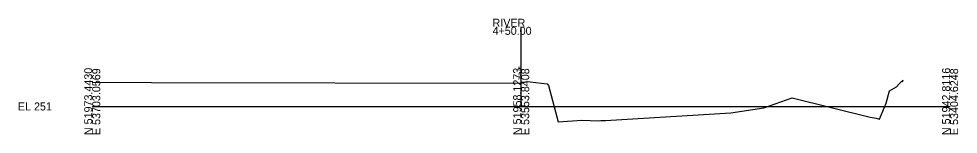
# Model space of a CAD drawing. Extents: x 5628 to 5956, y 92469 to 104012.
# Drawn here: x 5627.6 to 5956.2, y 93968.9 to 94009.2 of the extents above; entities that cross this region are included whole.
import ezdxf

# ---------------------------------------------------------------- set-up
doc = ezdxf.new("R2010")
doc.units = 0
for name, color, linetype in [('Level 10', 7, 'Continuous'), ('Level 60', 7, 'Continuous'), ('Level 63', 7, 'Continuous')]:
    doc.layers.add(name, color=color, linetype=linetype)

msp = doc.modelspace()

# ---------------------------------------------------------------- linework, layer by layer
at = {"layer": 'Level 60'}
for p, q in [((5653.34, 93987.08), (5674.06, 93986.92)), ((5674.06, 93986.92), (5802.45, 93986.7)), ((5802.45, 93986.7), (5803.34, 93986.7)), ((5803.34, 93986.7), (5804.95, 93987.23)), ((5804.95, 93987.23), (5805.38, 93987.35)), ((5805.38, 93987.35), (5806.47, 93987.21)), ((5806.47, 93987.21), (5812.44, 93986.46)), ((5812.44, 93986.46), (5812.92, 93985.94)), ((5934.64, 93985.48), (5935.58, 93986.47)), ((5935.58, 93986.47), (5936.41, 93987.44)), ((5936.41, 93987.44), (5936.73, 93987.24)), ((5936.73, 93987.24), (5936.97, 93987.87)), ((5812.92, 93985.94), (5816.27, 93973.28)), ((5931.03, 93979.72), (5932.18, 93984)), ((5932.18, 93984), (5934.64, 93985.48)), ((5888.18, 93978.07), (5898.12, 93981.63)), ((5898.12, 93981.63), (5925.36, 93974.86)), ((5876.68, 93976.31), (5888.18, 93978.07)), ((5928.6, 93974.16), (5931.03, 93979.72)), ((5816.27, 93973.28), (5824.54, 93973.78)), ((5824.54, 93973.78), (5830.39, 93973.53)), ((5830.39, 93973.53), (5831.15, 93973.72)), ((5831.15, 93973.72), (5832.83, 93973.74)), ((5832.83, 93973.74), (5876.68, 93976.31)), ((5925.36, 93974.86), (5927.49, 93974.52)), ((5927.49, 93974.52), (5928.6, 93974.16))]:
    msp.add_line(p, q, dxfattribs=at)
at = {"layer": 'Level 63'}
for p, q in [((5803.34, 93978.6), (5803.34, 94006.43)), ((5653.34, 93978.6), (5803.34, 93978.6)), ((5803.34, 93978.6), (5953.34, 93978.6))]:
    msp.add_line(p, q, dxfattribs=at)

# ---------------------------------------------------------------- texts
at = {"layer": 'Level 10'}
msp.add_text('255.05', height=1.2, rotation=90, dxfattribs=at).set_placement((5803.54, 93987.7))
at = {"layer": 'Level 63'}
for s, p in [('4+50.00', (5793.34, 94003.63)), ('RIVER', (5793.34, 94006.43)), ('EL 251', (5627.34, 93977.2))]:
    msp.add_text(s, height=2.8, dxfattribs=at).set_placement(p)
for s, p in [('N 51973.4430', (5653.34, 93968.6)), ('E 53703.0569', (5656.14, 93968.6)), ('N 51958.1273', (5803.34, 93968.59)), ('E 53553.8408', (5806.14, 93968.6)), ('N 51942.8116', (5953.34, 93968.59)), ('E 53404.6248', (5956.14, 93968.6))]:
    msp.add_text(s, height=2.8, rotation=90, dxfattribs=at).set_placement(p)

doc.saveas('drawing.dxf')
